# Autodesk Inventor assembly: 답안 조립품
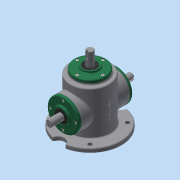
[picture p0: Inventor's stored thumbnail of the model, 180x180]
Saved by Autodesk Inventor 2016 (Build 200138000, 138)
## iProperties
Created: 2018-04
Part Number: 답안 조립품
Material: 일반
Document SubType Name: Assembly
Designer: 605-11
Author: 605-11
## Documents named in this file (16)
- C:\Users\605-11\Desktop\480407V1009\답안 조립품.iam
- C:\Users\605-11\Desktop\480407V1009\480407V1009\메인 베벨기어.ipt
- C:\Users\605-11\Desktop\480407V1009\480407V1009\메인 축.ipt
- 메인 축.ipt
- C:\Users\605-11\Desktop\480407V1009\480407V1009\베어링 6203.ipt
- C:\Users\605-11\Desktop\480407V1009\480407V1009\볼트 M4.ipt
- 볼트 M4.ipt
- C:\Users\605-11\Desktop\480407V1009\480407V1009\서브 베벨기어.ipt
- C:\Users\605-11\Desktop\480407V1009\480407V1009\서브 축.ipt
- 서브 축.ipt
- C:\Users\605-11\Desktop\480407V1009\480407V1009\오일 실.ipt
- 오일 실.ipt
- C:\Users\605-11\Desktop\480407V1009\480407V1009\커버.ipt
- C:\Users\605-11\Desktop\480407V1009\480407V1009\키 4x4.ipt
- C:\Users\605-11\Desktop\480407V1009\480407V1009\키 5x5.ipt
- C:\Users\605-11\Desktop\480407V1009\본체.ipt
